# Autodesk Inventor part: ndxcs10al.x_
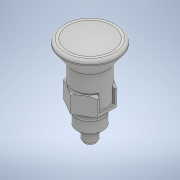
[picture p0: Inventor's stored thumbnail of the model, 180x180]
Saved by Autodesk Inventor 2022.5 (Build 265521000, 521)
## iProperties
Created: 2018-04
Part Number: ndxcs10al.x_
Material: 一般
Document SubType Name: Modeling
Designer: imaocorp
Density: 1 g/cm^3
Appearance: 既定
Sending System: SOLIDWORKS 2016-2016286
MC: AMD64
MC_MODEL: AMD64 Family 21 Model 2 Stepping 0, AuthenticAMD
OS: Windows_NT
FRU: Parasolid Version 28.0, build 224,  7-29-2016
FORMAT: text
GUISE: transmit
KEY: ndxcs10al
FILE: ndxcs10al.x_t
DATE: Wed Apr 25 10:17:22 2018
Author: imaocorp
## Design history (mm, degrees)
feature "Base1"
node "ソリッド1"
